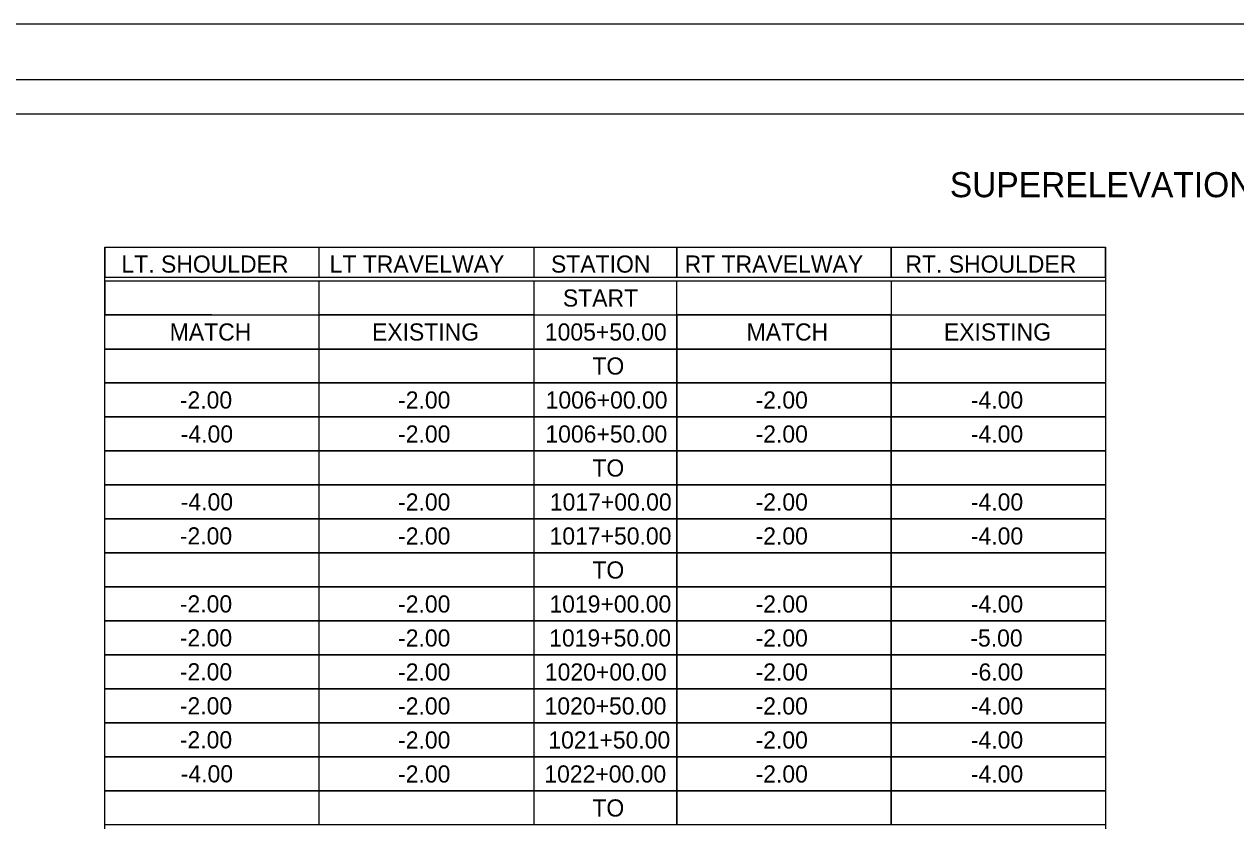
# Model space of a CAD drawing. Extents: x 1026502 to 1027102, y 781811 to 782040.
# Drawn here: x 1026652.77 to 1026686.67, y 781920.14 to 781942.42 of the extents above; entities that cross this region are included whole.
import ezdxf

# ---------------------------------------------------------------- set-up
doc = ezdxf.new("R2010")
doc.units = 0
for name, color, linetype in [('ANNOTATION', 7, 'Continuous'), ('BORDER', 7, 'Continuous'), ('DIMENSIONS', 7, 'Continuous'), ('JUNK', 7, 'Continuous'), ('PLOT BOUNDARY', 7, 'Continuous')]:
    doc.layers.add(name, color=color, linetype=linetype)

msp = doc.modelspace()

# ---------------------------------------------------------------- linework, layer by layer
at = {"layer": 'ANNOTATION'}
msp.add_lwpolyline([(1026655.027, 781936.19), (1026683.027, 781936.19), (1026683.027, 781882.017), (1026655.027, 781882.017)], close=True, dxfattribs=at)
at = {"layer": 'BORDER'}
for p, q in [((1026753.357, 781940.868), (1026625.357, 781940.868)), ((1026655.027, 781936.19), (1026655.027, 781935.345)), ((1026658.027, 781935.239), (1026655.027, 781935.239)), ((1026655.027, 781935.239), (1026655.027, 781934.289)), ((1026683.027, 781935.239), (1026683.027, 781934.289)), ((1026658.027, 781934.289), (1026655.027, 781934.289)), ((1026658.027, 781934.289), (1026655.027, 781934.289)), ((1026658.027, 781933.338), (1026655.027, 781933.338)), ((1026658.027, 781933.338), (1026655.027, 781933.338)), ((1026658.027, 781933.338), (1026661.027, 781933.338)), ((1026658.027, 781932.388), (1026655.027, 781932.388)), ((1026658.027, 781932.388), (1026655.027, 781932.388)), ((1026658.027, 781932.388), (1026661.027, 781932.388)), ((1026658.027, 781931.438), (1026655.027, 781931.438)), ((1026658.027, 781931.438), (1026655.027, 781931.438)), ((1026658.027, 781931.438), (1026661.027, 781931.438)), ((1026658.027, 781930.487), (1026655.027, 781930.487)), ((1026658.027, 781930.487), (1026655.027, 781930.487)), ((1026658.027, 781930.487), (1026661.027, 781930.487)), ((1026658.027, 781929.537), (1026655.027, 781929.537)), ((1026658.027, 781929.537), (1026655.027, 781929.537)), ((1026658.027, 781929.537), (1026661.027, 781929.537)), ((1026658.027, 781928.586), (1026655.027, 781928.586)), ((1026658.027, 781928.586), (1026655.027, 781928.586)), ((1026658.027, 781928.586), (1026661.027, 781928.586)), ((1026658.027, 781927.636), (1026655.027, 781927.636)), ((1026658.027, 781927.636), (1026655.027, 781927.636)), ((1026658.027, 781927.636), (1026661.027, 781927.636)), ((1026658.027, 781926.686), (1026655.027, 781926.686)), ((1026658.027, 781926.686), (1026655.027, 781926.686)), ((1026658.027, 781926.686), (1026661.027, 781926.686)), ((1026658.027, 781925.735), (1026655.027, 781925.735)), ((1026658.027, 781925.735), (1026655.027, 781925.735)), ((1026658.027, 781925.735), (1026661.027, 781925.735)), ((1026658.027, 781924.785), (1026655.027, 781924.785)), ((1026658.027, 781924.785), (1026655.027, 781924.785)), ((1026658.027, 781924.785), (1026661.027, 781924.785)), ((1026658.027, 781923.834), (1026655.027, 781923.834)), ((1026658.027, 781923.834), (1026655.027, 781923.834)), ((1026658.027, 781923.834), (1026661.027, 781923.834)), ((1026658.027, 781922.884), (1026655.027, 781922.884)), ((1026658.027, 781922.884), (1026655.027, 781922.884)), ((1026658.027, 781922.884), (1026661.027, 781922.884)), ((1026658.027, 781921.934), (1026655.027, 781921.934)), ((1026658.027, 781921.934), (1026655.027, 781921.934)), ((1026658.027, 781921.934), (1026661.027, 781921.934)), ((1026658.027, 781920.983), (1026655.027, 781920.983)), ((1026658.027, 781920.983), (1026655.027, 781920.983)), ((1026658.027, 781920.983), (1026661.027, 781920.983))]:
    msp.add_line(p, q, dxfattribs=at)
for points in [[(1026655.027, 781936.19), (1026683.027, 781936.19), (1026683.027, 781935.239), (1026655.027, 781935.239)], [(1026655.027, 781934.289), (1026683.027, 781934.289), (1026683.027, 781933.338), (1026655.027, 781933.338)], [(1026655.027, 781933.338), (1026683.027, 781933.338), (1026683.027, 781932.388), (1026655.027, 781932.388)], [(1026655.027, 781932.388), (1026683.027, 781932.388), (1026683.027, 781931.438), (1026655.027, 781931.438)], [(1026655.027, 781931.438), (1026683.027, 781931.438), (1026683.027, 781930.487), (1026655.027, 781930.487)], [(1026655.027, 781930.487), (1026683.027, 781930.487), (1026683.027, 781929.537), (1026655.027, 781929.537)], [(1026655.027, 781929.537), (1026683.027, 781929.537), (1026683.027, 781928.586), (1026655.027, 781928.586)], [(1026655.027, 781928.586), (1026683.027, 781928.586), (1026683.027, 781927.636), (1026655.027, 781927.636)], [(1026655.027, 781927.636), (1026683.027, 781927.636), (1026683.027, 781926.686), (1026655.027, 781926.686)], [(1026655.027, 781926.686), (1026683.027, 781926.686), (1026683.027, 781925.735), (1026655.027, 781925.735)], [(1026655.027, 781925.735), (1026683.027, 781925.735), (1026683.027, 781924.785), (1026655.027, 781924.785)], [(1026655.027, 781924.785), (1026683.027, 781924.785), (1026683.027, 781923.834), (1026655.027, 781923.834)], [(1026655.027, 781923.834), (1026683.027, 781923.834), (1026683.027, 781922.884), (1026655.027, 781922.884)], [(1026655.027, 781922.884), (1026683.027, 781922.884), (1026683.027, 781921.934), (1026655.027, 781921.934)], [(1026655.027, 781921.934), (1026683.027, 781921.934), (1026683.027, 781920.983), (1026655.027, 781920.983)], [(1026655.027, 781920.983), (1026683.027, 781920.983), (1026683.027, 781920.033), (1026655.027, 781920.033)]]:
    msp.add_lwpolyline(points, close=True, dxfattribs=at)
for points in [[(1026655.027, 781935.345), (1026683.027, 781935.345), (1026683.027, 781936.19)], [(1026661.027, 781935.345), (1026661.027, 781936.19)], [(1026667.027, 781936.19), (1026667.027, 781935.345)], [(1026671.027, 781936.19), (1026671.027, 781935.345)], [(1026671.027, 781935.345), (1026671.027, 781936.19)], [(1026677.027, 781936.19), (1026677.027, 781935.345)], [(1026677.027, 781935.345), (1026677.027, 781936.19)], [(1026683.027, 781936.19), (1026683.027, 781935.345)], [(1026667.027, 781935.239), (1026667.027, 781934.289), (1026661.027, 781934.289), (1026661.027, 781935.239)], [(1026677.027, 781935.239), (1026677.027, 781934.289), (1026671.027, 781934.289), (1026671.027, 781935.239)], [(1026667.027, 781934.289), (1026667.027, 781933.338), (1026661.027, 781933.338), (1026661.027, 781934.289)], [(1026671.027, 781934.289), (1026671.027, 781933.338), (1026667.027, 781933.338)], [(1026677.027, 781934.289), (1026677.027, 781933.338), (1026671.027, 781933.338), (1026671.027, 781934.289)], [(1026683.027, 781934.289), (1026683.027, 781933.338), (1026677.027, 781933.338), (1026677.027, 781934.289)], [(1026667.027, 781933.338), (1026667.027, 781932.388), (1026661.027, 781932.388), (1026661.027, 781933.338)], [(1026671.027, 781933.338), (1026671.027, 781932.388), (1026667.027, 781932.388)], [(1026677.027, 781933.338), (1026677.027, 781932.388), (1026671.027, 781932.388), (1026671.027, 781933.338)], [(1026683.027, 781933.338), (1026683.027, 781932.388), (1026677.027, 781932.388), (1026677.027, 781933.338)], [(1026667.027, 781932.388), (1026667.027, 781931.438), (1026661.027, 781931.438), (1026661.027, 781932.388)], [(1026671.027, 781932.388), (1026671.027, 781931.438), (1026667.027, 781931.438)], [(1026677.027, 781932.388), (1026677.027, 781931.438), (1026671.027, 781931.438), (1026671.027, 781932.388)], [(1026683.027, 781932.388), (1026683.027, 781931.438), (1026677.027, 781931.438), (1026677.027, 781932.388)], [(1026667.027, 781931.438), (1026667.027, 781930.487), (1026661.027, 781930.487), (1026661.027, 781931.438)], [(1026671.027, 781931.438), (1026671.027, 781930.487), (1026667.027, 781930.487)], [(1026677.027, 781931.438), (1026677.027, 781930.487), (1026671.027, 781930.487), (1026671.027, 781931.438)], [(1026683.027, 781931.438), (1026683.027, 781930.487), (1026677.027, 781930.487), (1026677.027, 781931.438)], [(1026667.027, 781930.487), (1026667.027, 781929.537), (1026661.027, 781929.537), (1026661.027, 781930.487)], [(1026671.027, 781930.487), (1026671.027, 781929.537), (1026667.027, 781929.537)], [(1026677.027, 781930.487), (1026677.027, 781929.537), (1026671.027, 781929.537), (1026671.027, 781930.487)], [(1026683.027, 781930.487), (1026683.027, 781929.537), (1026677.027, 781929.537), (1026677.027, 781930.487)], [(1026667.027, 781929.537), (1026667.027, 781928.586), (1026661.027, 781928.586), (1026661.027, 781929.537)], [(1026671.027, 781929.537), (1026671.027, 781928.586), (1026667.027, 781928.586)], [(1026677.027, 781929.537), (1026677.027, 781928.586), (1026671.027, 781928.586), (1026671.027, 781929.537)], [(1026683.027, 781929.537), (1026683.027, 781928.586), (1026677.027, 781928.586), (1026677.027, 781929.537)], [(1026667.027, 781928.586), (1026667.027, 781927.636), (1026661.027, 781927.636), (1026661.027, 781928.586)], [(1026671.027, 781928.586), (1026671.027, 781927.636), (1026667.027, 781927.636)], [(1026677.027, 781928.586), (1026677.027, 781927.636), (1026671.027, 781927.636), (1026671.027, 781928.586)], [(1026683.027, 781928.586), (1026683.027, 781927.636), (1026677.027, 781927.636), (1026677.027, 781928.586)], [(1026667.027, 781927.636), (1026667.027, 781926.686), (1026661.027, 781926.686), (1026661.027, 781927.636)], [(1026671.027, 781927.636), (1026671.027, 781926.686), (1026667.027, 781926.686)], [(1026677.027, 781927.636), (1026677.027, 781926.686), (1026671.027, 781926.686), (1026671.027, 781927.636)], [(1026683.027, 781927.636), (1026683.027, 781926.686), (1026677.027, 781926.686), (1026677.027, 781927.636)], [(1026667.027, 781926.686), (1026667.027, 781925.735), (1026661.027, 781925.735), (1026661.027, 781926.686)], [(1026671.027, 781926.686), (1026671.027, 781925.735), (1026667.027, 781925.735)], [(1026677.027, 781926.686), (1026677.027, 781925.735), (1026671.027, 781925.735), (1026671.027, 781926.686)], [(1026683.027, 781926.686), (1026683.027, 781925.735), (1026677.027, 781925.735), (1026677.027, 781926.686)], [(1026667.027, 781925.735), (1026667.027, 781924.785), (1026661.027, 781924.785), (1026661.027, 781925.735)], [(1026671.027, 781925.735), (1026671.027, 781924.785), (1026667.027, 781924.785)], [(1026677.027, 781925.735), (1026677.027, 781924.785), (1026671.027, 781924.785), (1026671.027, 781925.735)], [(1026683.027, 781925.735), (1026683.027, 781924.785), (1026677.027, 781924.785), (1026677.027, 781925.735)], [(1026667.027, 781924.785), (1026667.027, 781923.834), (1026661.027, 781923.834), (1026661.027, 781924.785)], [(1026671.027, 781924.785), (1026671.027, 781923.834), (1026667.027, 781923.834)], [(1026677.027, 781924.785), (1026677.027, 781923.834), (1026671.027, 781923.834), (1026671.027, 781924.785)], [(1026683.027, 781924.785), (1026683.027, 781923.834), (1026677.027, 781923.834), (1026677.027, 781924.785)], [(1026667.027, 781923.834), (1026667.027, 781922.884), (1026661.027, 781922.884), (1026661.027, 781923.834)], [(1026671.027, 781923.834), (1026671.027, 781922.884), (1026667.027, 781922.884)], [(1026677.027, 781923.834), (1026677.027, 781922.884), (1026671.027, 781922.884), (1026671.027, 781923.834)], [(1026683.027, 781923.834), (1026683.027, 781922.884), (1026677.027, 781922.884), (1026677.027, 781923.834)], [(1026667.027, 781922.884), (1026667.027, 781921.934), (1026661.027, 781921.934), (1026661.027, 781922.884)], [(1026671.027, 781922.884), (1026671.027, 781921.934), (1026667.027, 781921.934)], [(1026677.027, 781922.884), (1026677.027, 781921.934), (1026671.027, 781921.934), (1026671.027, 781922.884)], [(1026683.027, 781922.884), (1026683.027, 781921.934), (1026677.027, 781921.934), (1026677.027, 781922.884)], [(1026667.027, 781921.934), (1026667.027, 781920.983), (1026661.027, 781920.983), (1026661.027, 781921.934)], [(1026671.027, 781921.934), (1026671.027, 781920.983), (1026667.027, 781920.983)], [(1026677.027, 781921.934), (1026677.027, 781920.983), (1026671.027, 781920.983), (1026671.027, 781921.934)], [(1026683.027, 781921.934), (1026683.027, 781920.983), (1026677.027, 781920.983), (1026677.027, 781921.934)], [(1026667.027, 781920.983), (1026667.027, 781920.033), (1026661.027, 781920.033), (1026661.027, 781920.983)], [(1026671.027, 781920.983), (1026671.027, 781920.033), (1026667.027, 781920.033)], [(1026677.027, 781920.983), (1026677.027, 781920.033), (1026671.027, 781920.033), (1026671.027, 781920.983)], [(1026683.027, 781920.983), (1026683.027, 781920.033), (1026677.027, 781920.033), (1026677.027, 781920.983)]]:
    msp.add_lwpolyline(points, dxfattribs=at)
at = {"layer": 'JUNK'}
msp.add_lwpolyline([(1026626.458, 781939.919), (1026744.596, 781939.919), (1026744.596, 781857.651), (1026626.458, 781857.651)], close=True, dxfattribs=at)
at = {"layer": 'PLOT BOUNDARY'}
msp.add_lwpolyline([(1026618.883, 781854.421), (1026754.882, 781854.421), (1026754.882, 781942.421), (1026618.883, 781942.421)], close=True, dxfattribs=at)

# ---------------------------------------------------------------- texts
at = {"layer": 'ANNOTATION'}
msp.add_text('SUPERELEVATION TABLE', height=0.70123, dxfattribs=at).set_placement((1026678.668, 781937.583))
at = {"layer": 'DIMENSIONS'}
for s, p in [('LT. SHOULDER', (1026655.495, 781935.474)), ('LT TRAVELWAY', (1026661.318, 781935.474)), ('STATION', (1026667.511, 781935.474)), ('RT TRAVELWAY', (1026671.249, 781935.474)), ('RT. SHOULDER', (1026677.426, 781935.474)), ('START', (1026667.844, 781934.524)), ('MATCH', (1026656.844, 781933.574)), ('EXISTING', (1026662.503, 781933.574)), ('1005+50.00', (1026667.339, 781933.574)), ('MATCH', (1026672.983, 781933.574)), ('EXISTING', (1026678.503, 781933.574)), ('TO', (1026668.669, 781932.623)), ('-2.00', (1026657.128, 781931.673)), ('-2.00', (1026663.234, 781931.672)), ('1006+00.00', (1026667.361, 781931.672)), ('-2.00', (1026673.234, 781931.672)), ('-4.00', (1026679.257, 781931.672)), ('-4.00', (1026657.154, 781930.722)), ('-2.00', (1026663.234, 781930.721)), ('1006+50.00', (1026667.354, 781930.721)), ('-2.00', (1026673.234, 781930.721)), ('-4.00', (1026679.257, 781930.721)), ('TO', (1026668.669, 781929.77)), ('-4.00', (1026657.154, 781928.822)), ('-2.00', (1026663.234, 781928.82)), ('1017+00.00', (1026667.478, 781928.82)), ('-2.00', (1026673.234, 781928.82)), ('-4.00', (1026679.257, 781928.82)), ('-2.00', (1026657.128, 781927.871)), ('-2.00', (1026663.234, 781927.869)), ('1017+50.00', (1026667.471, 781927.869)), ('-2.00', (1026673.234, 781927.869)), ('-4.00', (1026679.257, 781927.869)), ('TO', (1026668.669, 781926.918)), ('-2.00', (1026657.128, 781925.97)), ('-2.00', (1026663.234, 781925.967)), ('1019+00.00', (1026667.467, 781925.967)), ('-2.00', (1026673.234, 781925.967)), ('-4.00', (1026679.257, 781925.967)), ('-2.00', (1026657.128, 781925.02)), ('-2.00', (1026663.234, 781925.016)), ('1019+50.00', (1026667.46, 781925.016)), ('-2.00', (1026673.234, 781925.016)), ('-5.00', (1026679.242, 781925.016)), ('-2.00', (1026657.128, 781924.07)), ('-2.00', (1026663.234, 781924.065)), ('1020+00.00', (1026667.339, 781924.065)), ('-2.00', (1026673.234, 781924.065)), ('-6.00', (1026679.257, 781924.065)), ('-2.00', (1026657.128, 781923.119)), ('-2.00', (1026663.234, 781923.115)), ('1020+50.00', (1026667.331, 781923.115)), ('-2.00', (1026673.234, 781923.115)), ('-4.00', (1026679.257, 781923.115)), ('-2.00', (1026657.128, 781922.169)), ('-2.00', (1026663.234, 781922.164)), ('1021+50.00', (1026667.437, 781922.164)), ('-2.00', (1026673.234, 781922.164)), ('-4.00', (1026679.257, 781922.164)), ('-4.00', (1026657.154, 781921.218)), ('-2.00', (1026663.234, 781921.213)), ('1022+00.00', (1026667.324, 781921.213)), ('-2.00', (1026673.234, 781921.213)), ('-4.00', (1026679.257, 781921.213)), ('TO', (1026668.669, 781920.262))]:
    msp.add_text(s, height=0.48, dxfattribs=at).set_placement(p)

doc.saveas('drawing.dxf')
